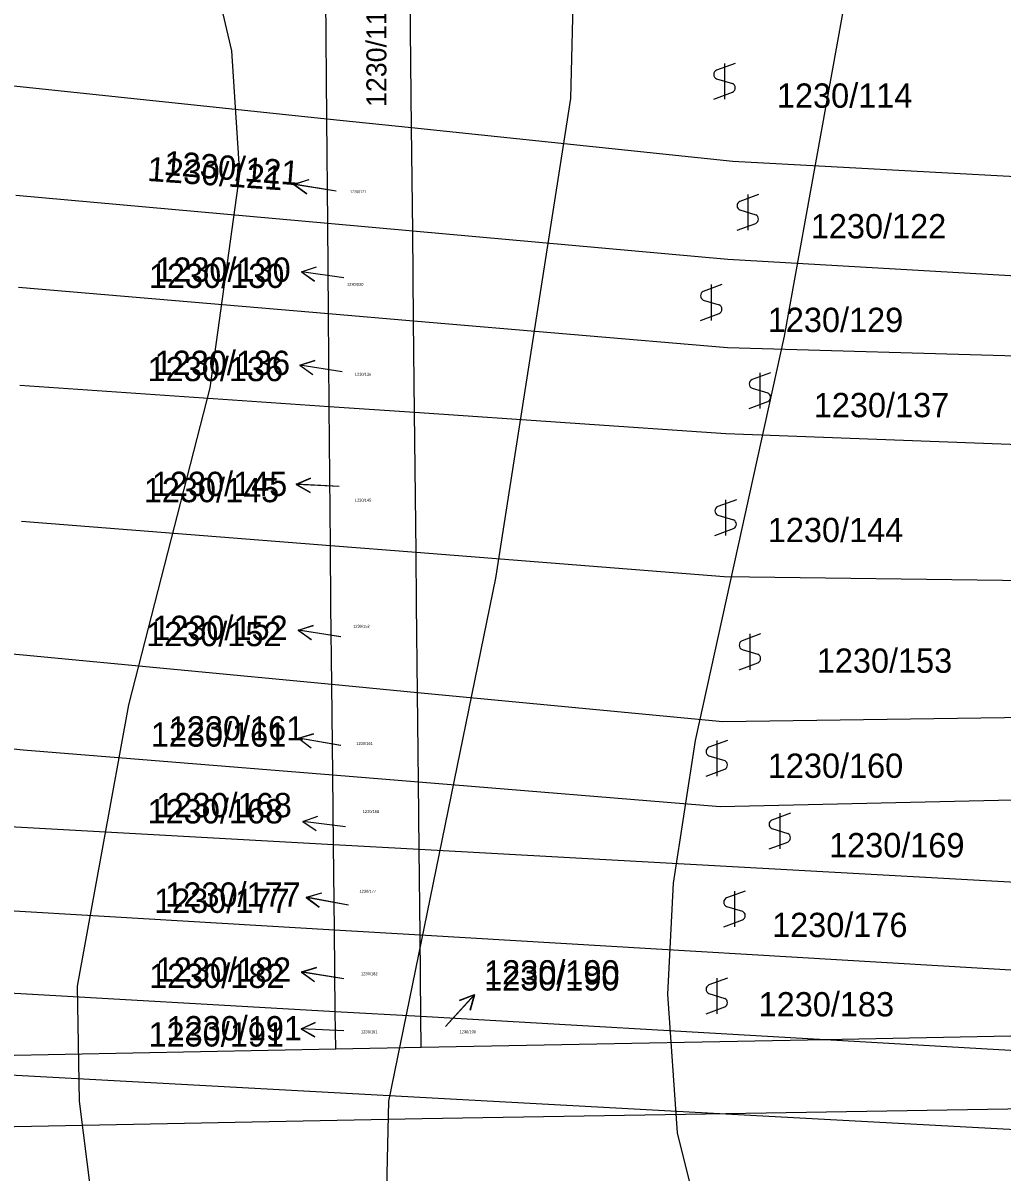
# Model space of a CAD drawing. Extents: x -555860 to -552701, y -1187050 to -1182291.
# Drawn here: x -554072.7 to -554004.1, y -1184713.8 to -1184633.4 of the extents above; entities that cross this region are included whole.
import ezdxf

# ---------------------------------------------------------------- set-up
doc = ezdxf.new("R2010")
doc.units = 0
for name, color, linetype in [('LEG_2b', 7, 'Continuous'), ('Level 16', 7, 'Continuous'), ('Level 25', 7, 'Continuous'), ('Level 41', 7, 'Continuous'), ('navrh_BV', 7, 'Continuous'), ('stav_BV', 7, 'Continuous')]:
    doc.layers.add(name, color=color, linetype=linetype)

msp = doc.modelspace()

# ---------------------------------------------------------------- linework, layer by layer
at = {"layer": 'Level 16'}
for p, q in [((-554053.696, -1184644.713), (-554052.632, -1184644.371)), ((-554050.731, -1184645.17), (-554053.696, -1184644.713)), ((-554053.696, -1184644.713), (-554052.784, -1184645.36)), ((-554053.16, -1184650.817), (-554052.098, -1184650.466)), ((-554050.191, -1184651.25), (-554053.16, -1184650.817)), ((-554053.16, -1184650.817), (-554052.242, -1184651.456)), ((-554053.262, -1184657.347), (-554052.194, -1184657.014)), ((-554050.301, -1184657.83), (-554053.262, -1184657.347)), ((-554053.262, -1184657.347), (-554052.355, -1184658.001)), ((-554053.518, -1184665.709), (-554052.497, -1184665.253)), ((-554050.521, -1184665.84), (-554053.518, -1184665.709)), ((-554053.518, -1184665.709), (-554052.541, -1184666.252)), ((-554053.372, -1184675.887), (-554052.304, -1184675.554)), ((-554050.411, -1184676.37), (-554053.372, -1184675.887)), ((-554053.372, -1184675.887), (-554052.465, -1184676.541)), ((-554053.367, -1184683.457), (-554052.296, -1184683.135)), ((-554050.411, -1184683.97), (-554053.367, -1184683.457)), ((-554053.367, -1184683.457), (-554052.467, -1184684.12)), ((-554053.058, -1184689.282), (-554052.005, -1184688.909)), ((-554050.081, -1184689.65), (-554053.058, -1184689.282)), ((-554053.058, -1184689.282), (-554052.127, -1184689.901)), ((-554052.811, -1184694.574), (-554051.737, -1184694.265)), ((-554049.861, -1184695.12), (-554052.811, -1184694.574)), ((-554052.811, -1184694.574), (-554051.919, -1184695.248)), ((-554053.152, -1184699.807), (-554052.084, -1184699.474)), ((-554050.191, -1184700.29), (-554053.152, -1184699.807)), ((-554053.152, -1184699.807), (-554052.245, -1184700.461)), ((-554043.069, -1184703.629), (-554041.046, -1184701.414)), ((-554041.046, -1184701.414), (-554042.09, -1184701.815)), ((-554041.046, -1184701.414), (-554041.351, -1184702.49)), ((-554053.187, -1184703.783), (-554052.164, -1184703.333)), ((-554050.191, -1184703.93), (-554053.187, -1184703.783)), ((-554053.187, -1184703.783), (-554052.213, -1184704.332))]:
    msp.add_line(p, q, dxfattribs=at)
at = {"layer": 'Level 25'}
for p, q in [((-554022.79, -1184636.24), (-554024.092, -1184636.715)), ((-554023.54, -1184636.24), (-554023.54, -1184638.74)), ((-554024.092, -1184637.318), (-554022.987, -1184637.651)), ((-554024.29, -1184638.74), (-554022.987, -1184638.254)), ((-554021.16, -1184645.42), (-554022.462, -1184645.895)), ((-554021.91, -1184645.42), (-554021.91, -1184647.92)), ((-554022.462, -1184646.498), (-554021.357, -1184646.831)), ((-554022.66, -1184647.92), (-554021.357, -1184647.434)), ((-554023.72, -1184651.72), (-554025.022, -1184652.195)), ((-554024.47, -1184651.72), (-554024.47, -1184654.22)), ((-554025.022, -1184652.798), (-554023.917, -1184653.131)), ((-554025.22, -1184654.22), (-554023.917, -1184653.734)), ((-554020.31, -1184657.89), (-554021.612, -1184658.365)), ((-554021.06, -1184657.89), (-554021.06, -1184660.39)), ((-554021.612, -1184658.968), (-554020.507, -1184659.301)), ((-554021.81, -1184660.39), (-554020.507, -1184659.904)), ((-554022.71, -1184666.77), (-554024.012, -1184667.245)), ((-554023.46, -1184666.77), (-554023.46, -1184669.27)), ((-554024.012, -1184667.848), (-554022.907, -1184668.181)), ((-554024.21, -1184669.27), (-554022.907, -1184668.784)), ((-554021.01, -1184676.16), (-554022.312, -1184676.635)), ((-554021.76, -1184676.16), (-554021.76, -1184678.66)), ((-554022.312, -1184677.238), (-554021.207, -1184677.571)), ((-554022.51, -1184678.66), (-554021.207, -1184678.174)), ((-554023.33, -1184683.61), (-554024.632, -1184684.085)), ((-554024.08, -1184683.61), (-554024.08, -1184686.11)), ((-554024.632, -1184684.688), (-554023.527, -1184685.021)), ((-554024.83, -1184686.11), (-554023.527, -1184685.624)), ((-554018.92, -1184688.7), (-554020.222, -1184689.175)), ((-554019.67, -1184688.7), (-554019.67, -1184691.2)), ((-554020.222, -1184689.778), (-554019.117, -1184690.111)), ((-554020.42, -1184691.2), (-554019.117, -1184690.714)), ((-554022.09, -1184694.15), (-554023.392, -1184694.625)), ((-554022.84, -1184694.15), (-554022.84, -1184696.65)), ((-554023.392, -1184695.228), (-554022.287, -1184695.561)), ((-554023.59, -1184696.65), (-554022.287, -1184696.164)), ((-554023.33, -1184700.24), (-554024.632, -1184700.715)), ((-554024.08, -1184700.24), (-554024.08, -1184702.74)), ((-554024.632, -1184701.318), (-554023.527, -1184701.651)), ((-554024.83, -1184702.74), (-554023.527, -1184702.254))]:
    msp.add_line(p, q, dxfattribs=at)
for centre, start, end in [((-554023.96, -1184637.017), 113.579, 246.421), ((-554023.119, -1184637.953), 293.574, 66.42599), ((-554022.33, -1184646.197), 113.579, 246.421), ((-554021.489, -1184647.133), 293.574, 66.42599), ((-554024.89, -1184652.497), 113.579, 246.421), ((-554024.049, -1184653.433), 293.574, 66.42599), ((-554021.48, -1184658.667), 113.579, 246.421), ((-554020.639, -1184659.603), 293.574, 66.42599), ((-554023.88, -1184667.547), 113.579, 246.421), ((-554023.039, -1184668.483), 293.574, 66.42599), ((-554022.18, -1184676.937), 113.579, 246.421), ((-554021.339, -1184677.873), 293.574, 66.42599), ((-554024.5, -1184684.387), 113.579, 246.421), ((-554023.659, -1184685.323), 293.574, 66.42599), ((-554020.09, -1184689.477), 113.579, 246.421), ((-554019.249, -1184690.413), 293.574, 66.42599), ((-554023.26, -1184694.927), 113.579, 246.421), ((-554022.419, -1184695.863), 293.574, 66.42599), ((-554024.5, -1184701.017), 113.579, 246.421), ((-554023.659, -1184701.953), 293.574, 66.42599)]:
    msp.add_arc(centre, 0.329, start, end, dxfattribs=at)
at = {"layer": 'Level 41'}
for points in [[(-553918.169, -1184785.6), (-553920.89, -1184786.082), (-553934.34, -1184785.944), (-553954.861, -1184781.506), (-553964.567, -1184777.623), (-553982.315, -1184768.749), (-553990.773, -1184763.62), (-553997.845, -1184757.934), (-554004.084, -1184751.834), (-554015.038, -1184738.246), (-554021.833, -1184726.598), (-554024.883, -1184718.834), (-554026.824, -1184711.069), (-554027.517, -1184701.363), (-554027.102, -1184693.598), (-554025.576, -1184683.615), (-554019.337, -1184655.329), (-554011.572, -1184612.345)], [(-553916.089, -1184812.751), (-553926.298, -1184822.826), (-553929.903, -1184825.322), (-553935.727, -1184827.68), (-553940.204, -1184828.586), (-553944.601, -1184828.926), (-553951.256, -1184827.541), (-553979.542, -1184814.646), (-553998.4, -1184804.246), (-554009.631, -1184796.204), (-554024.883, -1184782.892), (-554035.421, -1184770.969), (-554050.673, -1184751.556), (-554059.963, -1184736.027), (-554064.917, -1184725.203), (-554066.758, -1184720.498), (-554067.887, -1184715.302), (-554068.699, -1184708.851), (-554068.837, -1184700.808), (-554065.232, -1184681.118), (-554059.547, -1184658.933), (-554057.467, -1184643.959), (-554058.022, -1184635.362), (-554060.102, -1184626.489)], [(-554034.11, -1184630.234), (-554034.312, -1184638.689), (-554039.581, -1184672.244), (-554047.068, -1184708.85), (-554047.207, -1184714.951), (-554046.236, -1184720.774), (-554044.82, -1184725.368), (-554042.354, -1184732.145), (-554034.728, -1184744.347), (-554024.467, -1184756.549), (-554018.089, -1184762.927), (-554007.551, -1184771.523), (-553979.82, -1184788.578), (-553971.5, -1184792.6), (-553961.457, -1184796.575), (-553946.542, -1184801.334), (-553940.996, -1184801.888), (-553934.593, -1184801.689), (-553922.97, -1184800.364), (-553917.558, -1184798.476)]]:
    msp.add_lwpolyline(points, dxfattribs=at)
at = {"layer": 'navrh_BV'}
for p, q in [((-554051.38, -1184640.11), (-554051.48, -1184627.91)), ((-554045.44, -1184640.73), (-554045.57, -1184628.5)), ((-554073.29, -1184637.82), (-554051.38, -1184640.11)), ((-554051.38, -1184640.11), (-554045.44, -1184640.73)), ((-554051.31, -1184647.44), (-554051.38, -1184640.11)), ((-554045.44, -1184640.73), (-554022.96, -1184643.08)), ((-554045.36, -1184647.98), (-554045.44, -1184640.73)), ((-554022.96, -1184643.08), (-553984.37, -1184645.19)), ((-554051.31, -1184647.44), (-554073.15, -1184645.48)), ((-554045.36, -1184647.98), (-554051.31, -1184647.44)), ((-554051.26, -1184653.74), (-554051.31, -1184647.44)), ((-554023.3, -1184649.96), (-554045.36, -1184647.98)), ((-554045.3, -1184654.25), (-554045.36, -1184647.98)), ((-553984.31, -1184652.2), (-554023.3, -1184649.96)), ((-554072.96, -1184651.89), (-554051.26, -1184653.74)), ((-554051.26, -1184653.74), (-554045.3, -1184654.25)), ((-554051.21, -1184660.26), (-554051.26, -1184653.74)), ((-554045.3, -1184654.25), (-554023.33, -1184656.12)), ((-554045.23, -1184660.67), (-554045.3, -1184654.25)), ((-554023.33, -1184656.12), (-553984.26, -1184657.24)), ((-554051.21, -1184660.26), (-554072.86, -1184658.77)), ((-554045.23, -1184660.67), (-554051.21, -1184660.26)), ((-554051.13, -1184669.97), (-554051.21, -1184660.26)), ((-554023.44, -1184662.16), (-554045.23, -1184660.67)), ((-554045.13, -1184670.44), (-554045.23, -1184660.67)), ((-553984.2, -1184663.62), (-554023.44, -1184662.16)), ((-554072.76, -1184668.26), (-554051.13, -1184669.97)), ((-554072.63, -1184677.65), (-554159.48, -1184669.42)), ((-554051.13, -1184669.97), (-554045.13, -1184670.44)), ((-554051.09, -1184674.2), (-554051.13, -1184669.97)), ((-554045.13, -1184670.44), (-554023.56, -1184672.14)), ((-554045.09, -1184674.08), (-554045.13, -1184670.44)), ((-554023.56, -1184672.14), (-553984.11, -1184672.66)), ((-554045.03, -1184680.27), (-554045.09, -1184674.08)), ((-554051.03, -1184679.7), (-554051.09, -1184674.2)), ((-554159.6, -1184675.67), (-554072.64, -1184684.26)), ((-554051.03, -1184679.7), (-554072.63, -1184677.65)), ((-554045.03, -1184680.27), (-554051.03, -1184679.7)), ((-554050.96, -1184686.02), (-554051.03, -1184679.7)), ((-554023.65, -1184682.3), (-554045.03, -1184680.27)), ((-554044.96, -1184686.51), (-554045.03, -1184680.27)), ((-553984.02, -1184681.73), (-554023.65, -1184682.3)), ((-554072.64, -1184684.26), (-554050.96, -1184686.02)), ((-554050.96, -1184686.02), (-554044.96, -1184686.51)), ((-554050.91, -1184690.9), (-554050.96, -1184686.02)), ((-554044.96, -1184686.51), (-554023.84, -1184688.23)), ((-554044.91, -1184691.23), (-554044.96, -1184686.51)), ((-554023.84, -1184688.23), (-553983.97, -1184687.33)), ((-554050.91, -1184690.9), (-554085.3, -1184689)), ((-554044.91, -1184691.23), (-554050.91, -1184690.9)), ((-554050.85, -1184696.85), (-554050.91, -1184690.9)), ((-553998.65, -1184693.79), (-554044.91, -1184691.23)), ((-554044.85, -1184697.21), (-554044.91, -1184691.23)), ((-554085.55, -1184694.8), (-554050.85, -1184696.85)), ((-554050.85, -1184696.85), (-554044.85, -1184697.21)), ((-554050.79, -1184702.59), (-554050.85, -1184696.85)), ((-554044.85, -1184697.21), (-553998.29, -1184699.96)), ((-554044.79, -1184702.93), (-554044.85, -1184697.21)), ((-554050.79, -1184702.59), (-554085.87, -1184700.58)), ((-554044.79, -1184702.93), (-554050.79, -1184702.59)), ((-554050.76, -1184705.2), (-554050.79, -1184702.59)), ((-554016.49, -1184704.55), (-554044.79, -1184702.93)), ((-554044.77, -1184705.08), (-554044.79, -1184702.93)), ((-554016.49, -1184704.55), (-554044.77, -1184705.08)), ((-553983.81, -1184703.93), (-554016.49, -1184704.55)), ((-553998.06, -1184705.6), (-554016.49, -1184704.55)), ((-554050.76, -1184705.2), (-554089.74, -1184705.97)), ((-554044.77, -1184705.08), (-554050.76, -1184705.2)), ((-554085.9, -1184706.34), (-554023.44, -1184709.73)), ((-553923.05, -1184708.08), (-554023.44, -1184709.73)), ((-554044.71, -1184710.08), (-554098.39, -1184711.14)), ((-554023.44, -1184709.73), (-554044.71, -1184710.08)), ((-554023.44, -1184709.73), (-553997.65, -1184711.13))]:
    msp.add_line(p, q, dxfattribs=at)
at = {"layer": 'stav_BV'}
for p, q in [((-554053.694, -1184644.701), (-554052.627, -1184644.363)), ((-554050.73, -1184645.17), (-554053.694, -1184644.701)), ((-554053.694, -1184644.701), (-554052.783, -1184645.352)), ((-554053.162, -1184650.832), (-554052.1, -1184650.476)), ((-554050.19, -1184651.25), (-554053.162, -1184650.832)), ((-554053.162, -1184650.832), (-554052.24, -1184651.468)), ((-554053.264, -1184657.361), (-554052.197, -1184657.023)), ((-554050.3, -1184657.83), (-554053.264, -1184657.361)), ((-554053.264, -1184657.361), (-554052.353, -1184658.012)), ((-554053.517, -1184665.683), (-554052.491, -1184665.235)), ((-554050.52, -1184665.84), (-554053.517, -1184665.683)), ((-554053.517, -1184665.683), (-554052.543, -1184666.235)), ((-554053.374, -1184675.901), (-554052.307, -1184675.563)), ((-554050.41, -1184676.37), (-554053.374, -1184675.901)), ((-554053.374, -1184675.901), (-554052.463, -1184676.552)), ((-554053.365, -1184683.449), (-554052.292, -1184683.13)), ((-554050.41, -1184683.97), (-554053.365, -1184683.449)), ((-554053.365, -1184683.449), (-554052.466, -1184684.116)), ((-554053.059, -1184689.284), (-554052.004, -1184688.909)), ((-554050.08, -1184689.65), (-554053.059, -1184689.284)), ((-554053.059, -1184689.284), (-554052.126, -1184689.903)), ((-554052.815, -1184694.599), (-554051.742, -1184694.28)), ((-554049.86, -1184695.12), (-554052.815, -1184694.599)), ((-554052.815, -1184694.599), (-554051.916, -1184695.266)), ((-554053.154, -1184699.821), (-554052.087, -1184699.483)), ((-554050.19, -1184700.29), (-554053.154, -1184699.821)), ((-554053.154, -1184699.821), (-554052.243, -1184700.472)), ((-554043.07, -1184703.63), (-554041.062, -1184701.4)), ((-554041.062, -1184701.4), (-554042.104, -1184701.809)), ((-554041.062, -1184701.4), (-554041.36, -1184702.479)), ((-554053.187, -1184703.773), (-554052.161, -1184703.325)), ((-554050.19, -1184703.93), (-554053.187, -1184703.773)), ((-554053.187, -1184703.773), (-554052.213, -1184704.325))]:
    msp.add_line(p, q, dxfattribs=at)

# ---------------------------------------------------------------- texts
at = {"layer": 'LEG_2b'}
for s, height, rotation, p in [('1230/115', 1.4, 90, (-554047.21, -1184639.29)), ('1230/121', 1.7, 356, (-554063.99, -1184644.46))]:
    msp.add_text(s, height=height, rotation=rotation, dxfattribs=at).set_placement(p)
for s, height, p in [('1230/114', 1.7, (-554019.87, -1184639.345)), ('1230/121', 0.2, (-554049.75, -1184645.32)), ('1230/122', 1.7, (-554017.5, -1184648.485)), ('1230/130', 1.7, (-554063.834, -1184651.952)), ('1230/130', 0.2, (-554049.97, -1184651.8)), ('1230/129', 1.7, (-554020.51, -1184655.035)), ('1230/136', 1.7, (-554063.924, -1184658.472)), ('1230/136', 0.2, (-554049.42, -1184658.09)), ('1230/137', 1.7, (-554017.29, -1184660.995)), ('1230/145', 1.7, (-554064.194, -1184666.942)), ('1230/145', 0.2, (-554049.42, -1184666.9)), ('1230/144', 1.7, (-554020.51, -1184669.735)), ('1230/152', 1.7, (-554064.034, -1184677.012)), ('1230/152', 0.2, (-554049.53, -1184675.72)), ('1230/153', 1.7, (-554017.08, -1184678.875)), ('1230/161', 1.7, (-554063.704, -1184684.042)), ('1230/161', 0.2, (-554049.31, -1184683.92)), ('1230/160', 1.7, (-554020.51, -1184686.225)), ('1230/168', 1.7, (-554063.924, -1184689.412)), ('1230/168', 0.2, (-554048.87, -1184688.68)), ('1230/169', 1.7, (-554016.22, -1184691.785)), ('1230/177', 1.7, (-554063.474, -1184695.672)), ('1230/177', 0.2, (-554049.09, -1184694.26)), ('1230/176', 1.7, (-554020.21, -1184697.365)), ('1230/182', 1.7, (-554063.824, -1184700.922)), ('1230/190', 1.7, (-554040.37, -1184701.105)), ('1230/182', 0.2, (-554048.98, -1184700.03)), ('1230/183', 1.7, (-554021.15, -1184702.915)), ('1230/191', 1.7, (-554063.864, -1184705.022)), ('1230/191', 0.2, (-554048.98, -1184704.09)), ('1230/190', 0.2, (-554042.09, -1184704.09))]:
    msp.add_text(s, height=height, dxfattribs=at).set_placement(p)
at = {"layer": 'Level 16'}
msp.add_text('1230/121', height=1.7, rotation=355.5, dxfattribs=at).set_placement((-554062.837, -1184644.034))
for s, p in [('1230/130', (-554063.391, -1184651.52)), ('1230/136', (-554063.434, -1184658.04)), ('1230/145', (-554063.633, -1184666.51)), ('1230/152', (-554063.603, -1184676.58)), ('1230/161', (-554062.446, -1184683.61)), ('1230/168', (-554063.316, -1184688.98)), ('1230/177', (-554062.688, -1184695.24)), ('1230/182', (-554063.357, -1184700.49)), ('1230/190', (-554040.37, -1184700.68)), ('1230/191', (-554062.606, -1184704.59))]:
    msp.add_text(s, height=1.7, dxfattribs=at).set_placement(p)

doc.saveas('drawing.dxf')
